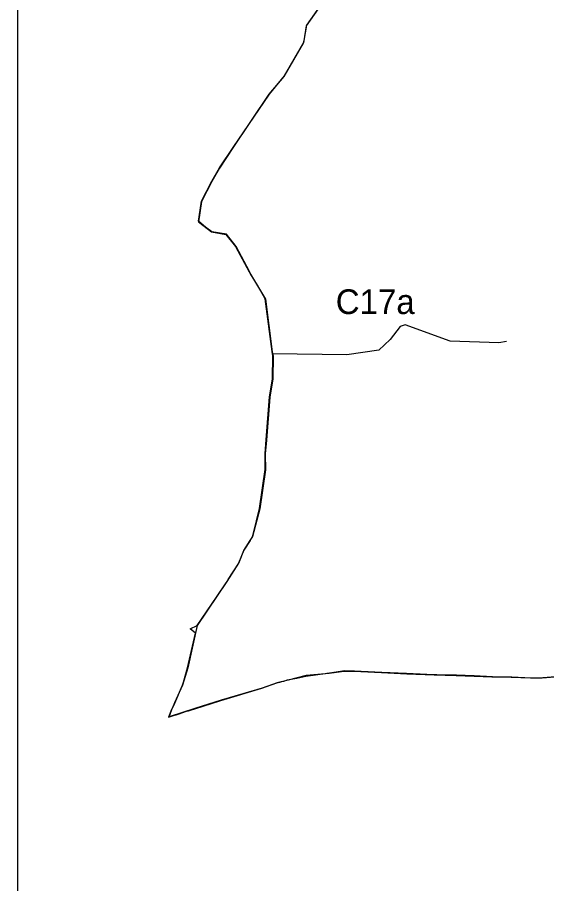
# Model space of a CAD drawing. Extents: x -478490 to -472450, y -1118050 to -1109550.
# Drawn here: x -478440 to -477155, y -1113725 to -1111620 of the extents above; entities that cross this region are included whole.
import ezdxf

# ---------------------------------------------------------------- set-up
doc = ezdxf.new("R2010")
doc.units = 0
for name, color, linetype in [('hranice kú', 7, 'Continuous'), ('Implicitní', 7, 'Continuous'), ('ObPÚ', 7, 'Continuous')]:
    doc.layers.add(name, color=color, linetype=linetype)

msp = doc.modelspace()

# ---------------------------------------------------------------- linework, layer by layer
at = {"layer": 'hranice kú'}
for p, q in [((-477658.2, -1111526.7), (-477738.5, -1111640.6)), ((-477738.5, -1111640.6), (-477743.9, -1111676.8)), ((-477745.7, -1111682.6), (-477792.7, -1111763.5)), ((-477743.9, -1111676.8), (-477745.7, -1111682.6)), ((-477792.7, -1111763.5), (-477829.2, -1111807.1)), ((-477829.2, -1111807.1), (-477917, -1111937.1)), ((-477917, -1111937.1), (-477949.4, -1111986.8)), ((-477949.4, -1111986.8), (-477967.8, -1112018.8)), ((-477967.8, -1112018.8), (-477992.9, -1112067.5)), ((-477992.9, -1112067.5), (-478000.3, -1112116.6)), ((-478000.3, -1112116.6), (-477968.7, -1112141.6)), ((-477968.7, -1112141.6), (-477933.8, -1112147.4)), ((-477933.8, -1112147.4), (-477910, -1112176.7)), ((-477910, -1112176.7), (-477876.7, -1112238.2)), ((-477876.7, -1112238.2), (-477873.6, -1112244)), ((-477873.6, -1112244), (-477837.5, -1112304.5)), ((-477837.5, -1112304.5), (-477821.5, -1112432.6)), ((-477821.5, -1112432.6), (-477819.1, -1112443.3)), ((-477819.1, -1112443.3), (-477819.9, -1112498.8)), ((-477819.9, -1112498.8), (-477826.9, -1112542.9)), ((-477826.9, -1112542.9), (-477835, -1112647.4)), ((-477835, -1112647.4), (-477838.2, -1112680.3)), ((-477838.2, -1112680.3), (-477837.4, -1112719.6)), ((-477837.4, -1112719.6), (-477851.4, -1112814.1)), ((-477851.4, -1112814.1), (-477868.8, -1112881.8)), ((-477871.9, -1112886.5), (-477874.9, -1112891.3)), ((-477868.8, -1112881.8), (-477871.9, -1112886.5)), ((-477874.9, -1112891.3), (-477889.7, -1112914.6)), ((-477889.7, -1112914.6), (-477902.7, -1112946.6)), ((-477902.7, -1112946.6), (-477931, -1112990.8)), ((-477931, -1112990.8), (-478003, -1113097.4)), ((-478003, -1113097.4), (-478026.4, -1113200.7)), ((-478026.4, -1113200.7), (-478038.6, -1113243)), ((-477766.4, -1113226.5), (-477761.5, -1113225.5)), ((-477761.5, -1113225.5), (-477739.4, -1113221.1)), ((-477739.4, -1113221.1), (-477692.8, -1113214.3)), ((-477692.8, -1113214.3), (-477683, -1113213.2)), ((-477683, -1113213.2), (-477646.5, -1113209)), ((-477646.5, -1113209), (-477622.5, -1113208.8)), ((-477622.5, -1113208.8), (-477556, -1113211.8)), ((-477556, -1113211.8), (-477494.1, -1113214.8)), ((-477494.1, -1113214.8), (-477427.6, -1113217.5)), ((-477427.6, -1113217.5), (-477374.1, -1113218.9)), ((-477374.1, -1113218.9), (-477330.4, -1113220.6)), ((-477330.4, -1113220.6), (-477287.5, -1113222.1)), ((-477287.5, -1113222.1), (-477240.8, -1113223)), ((-477240.8, -1113223), (-477193.8, -1113225.2)), ((-477193.8, -1113225.2), (-477165.8, -1113224.6)), ((-477165.8, -1113224.6), (-477134.7, -1113222.1)), ((-478038.6, -1113243), (-478058.5, -1113286)), ((-477846.5, -1113249.7), (-477810.1, -1113237.4)), ((-477810.1, -1113237.4), (-477802.8, -1113235.4)), ((-477802.8, -1113235.4), (-477797.7, -1113234)), ((-477797.7, -1113234), (-477792.8, -1113232.8)), ((-477792.8, -1113232.8), (-477783.8, -1113230)), ((-477783.8, -1113230), (-477771.4, -1113227.5)), ((-477771.4, -1113227.5), (-477766.4, -1113226.5)), ((-477945.6, -1113279.7), (-477846.5, -1113249.7)), ((-478058.5, -1113286), (-478062.4, -1113295)), ((-478009.3, -1113300.1), (-477945.6, -1113279.7)), ((-478065.9, -1113301.8), (-478072.8, -1113320.4)), ((-478062.4, -1113295), (-478065.9, -1113301.8)), ((-478049.8, -1113313.1), (-478028.9, -1113306.3)), ((-478028.9, -1113306.3), (-478024.4, -1113304.9)), ((-478024.4, -1113304.9), (-478019.9, -1113303.5)), ((-478019.9, -1113303.5), (-478009.3, -1113300.1)), ((-478072.8, -1113320.4), (-478058.8, -1113315.9)), ((-478058.8, -1113315.9), (-478054.3, -1113314.5)), ((-478054.3, -1113314.5), (-478049.8, -1113313.1))]:
    msp.add_line(p, q, dxfattribs=at)
at = {"layer": 'Implicitní'}
msp.add_lwpolyline([(-478440.1, -1118000.1), (-472500.1, -1118000.1), (-472500.1, -1109600.1), (-478440.1, -1109600.1)], close=True, dxfattribs=at)
msp.add_lwpolyline([(-477252.1, -1112407.9), (-477271, -1112410.6), (-477388.8, -1112406.9), (-477498.3, -1112367.2), (-477510.5, -1112370.9), (-477534.4, -1112402.8), (-477562.2, -1112428.8), (-477639.7, -1112440.1), (-477820.3, -1112437.9)], dxfattribs=at)
at = {"layer": 'ObPÚ'}
for points in [[(-477835.4, -1112646.6), (-477827.3, -1112542.4), (-477820, -1112498.1), (-477819.2, -1112442.7), (-477821.6, -1112432.3), (-477838, -1112304.3), (-477857.1, -1112270.7), (-477873.5, -1112243), (-477876.4, -1112237.5), (-477908.6, -1112176.5), (-477932.5, -1112147.3), (-477968.1, -1112141.6), (-477983.2, -1112129.6), (-478000.1, -1112115.6), (-477992.6, -1112066.4), (-477967.7, -1112017.9), (-477949, -1111986), (-477916, -1111936), (-477827.8, -1111806.6), (-477791.1, -1111762.3), (-477744.4, -1111681.6), (-477737.4, -1111639.5), (-477657.3, -1111525.4)], [(-477133.3, -1113222.8), (-477164, -1113225.1), (-477192.4, -1113225.6), (-477239.2, -1113223.4), (-477286.2, -1113222.1), (-477330.8, -1113220.4), (-477373.9, -1113218.6), (-477420.9, -1113217.5), (-477422.1, -1113217.6), (-477424.2, -1113217.6), (-477428.8, -1113217.3), (-477494.8, -1113214.2), (-477554.5, -1113211.8), (-477621.5, -1113208.7), (-477644.7, -1113208.3), (-477682.1, -1113213.5), (-477685.9, -1113214), (-477688.8, -1113214.4), (-477691.7, -1113214.8), (-477738.6, -1113219.4), (-477782.5, -1113230.5), (-477809, -1113237.3), (-477845.5, -1113249.8), (-477945.1, -1113279.5), (-478009.4, -1113299.8), (-478071.7, -1113319.9), (-478064.8, -1113301.6), (-478057.7, -1113286.3), (-478038.7, -1113242.8), (-478036.7, -1113235.8), (-478026.6, -1113200.8), (-478007.7, -1113116.1), (-478020.6, -1113106), (-478003, -1113097.8), (-478003, -1113097.8), (-477955, -1113026.7), (-477932.9, -1112994), (-477930.9, -1112991), (-477927.8, -1112986.2), (-477902.4, -1112946.7), (-477898.9, -1112938.5), (-477889.8, -1112915.2), (-477874.4, -1112891.1), (-477871.5, -1112886.6), (-477868.9, -1112882), (-477862.7, -1112857.3), (-477855.8, -1112829.9), (-477851.7, -1112813.6), (-477838.1, -1112718.8), (-477838.2, -1112715), (-477838.5, -1112680.1), (-477835.4, -1112646.6)]]:
    msp.add_lwpolyline(points, dxfattribs=at)

# ---------------------------------------------------------------- texts
at = {"layer": 'Implicitní'}
msp.add_text('C17a', height=60, dxfattribs=at).set_placement((-477666.8, -1112341))

doc.saveas('drawing.dxf')
